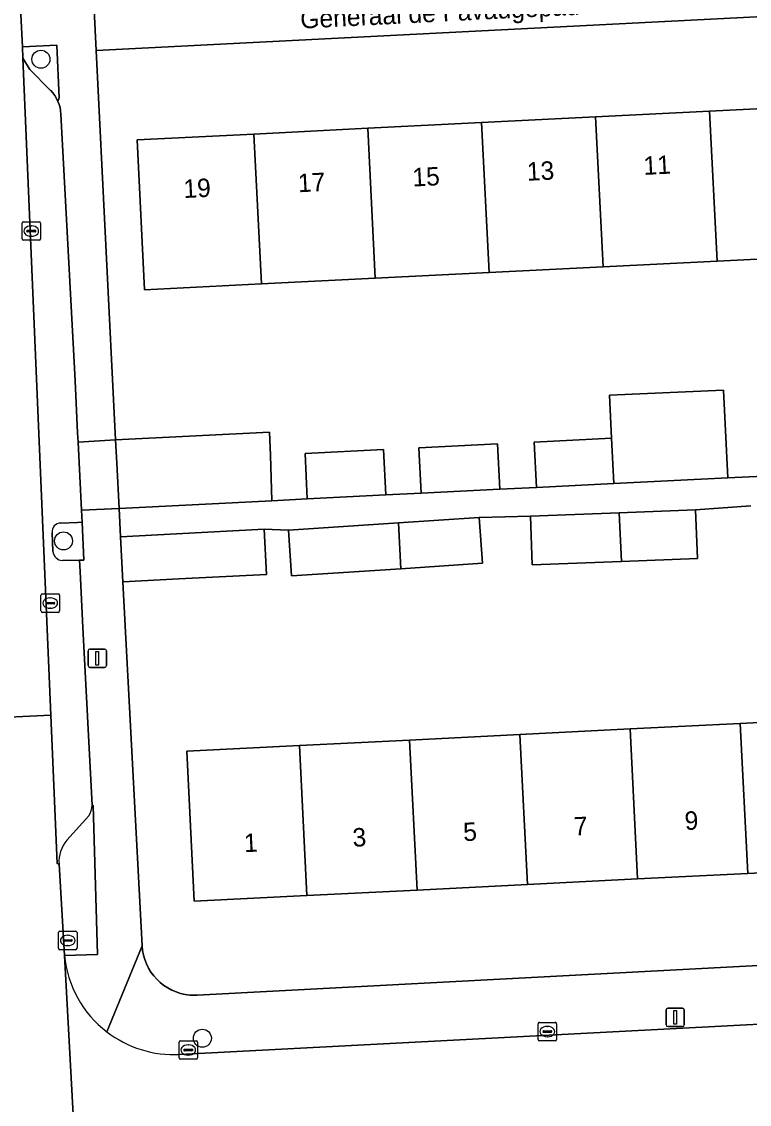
# Model space of a CAD drawing. Extents: x 161084 to 161928, y 385354 to 386522.
# Drawn here: x 161331.4 to 161370.9, y 385913.5 to 385972.3 of the extents above; entities that cross this region are included whole.
import ezdxf

# ---------------------------------------------------------------- set-up
doc = ezdxf.new("R2010")
doc.units = 0
for name, color, linetype in [('IMGEO_Boom', 7, 'Continuous'), ('IMGEO_Erf', 7, 'Continuous'), ('IMGEO_Groenvoorziening', 7, 'Continuous'), ('IMGEO_Kolk', 7, 'Continuous'), ('IMGEO_Lichtmast', 7, 'Continuous'), ('IMGEO_Openbare_ruimte_label', 7, 'Continuous'), ('IMGEO_Pand', 7, 'Continuous'), ('IMGEO_Pand_nummerreeks', 7, 'Continuous'), ('IMGEO_Parkeervlak_open', 7, 'Continuous'), ('IMGEO_Rijbaan_lokaal_open', 7, 'Continuous'), ('IMGEO_Voetpad_open', 7, 'Continuous')]:
    doc.layers.add(name, color=color, linetype=linetype)

msp = doc.modelspace()

# ---------------------------------------------------------------- linework, layer by layer
at = {"layer": 'IMGEO_Boom'}
for centre in [(161332.478, 385970.242), (161333.705, 385944.1), (161341.242, 385917.109)]:
    msp.add_circle(centre, 0.489, dxfattribs=at)
at = {"layer": 'IMGEO_Erf'}
for points in [[(161401.475, 385974.097), (161335.484, 385970.716), (161336.531, 385949.582), (161344.88, 385950.003), (161344.943, 385948.749), (161345.008, 385946.283), (161346.937, 385946.38), (161346.814, 385948.843), (161351.074, 385949.057), (161351.197, 385946.594), (161353.118, 385946.691), (161352.995, 385949.154), (161357.262, 385949.368), (161357.386, 385946.905), (161359.369, 385947.005), (161359.245, 385949.468), (161363.452, 385949.679), (161363.335, 385952.014), (161369.526, 385952.286), (161369.764, 385947.527), (161371.701, 385947.624)], [(161375.356, 385959.598), (161369.174, 385959.288), (161362.991, 385958.977), (161356.809, 385958.667), (161350.627, 385958.357), (161344.445, 385958.046), (161338.11, 385957.728), (161337.701, 385965.867), (161344.036, 385966.185), (161350.218, 385966.496), (161356.4, 385966.806), (161362.582, 385967.116), (161368.765, 385967.427), (161374.947, 385967.737)], [(161371.013, 385946.014), (161368.009, 385945.788), (161368.11, 385943.145), (161363.994, 385942.988), (161359.147, 385942.802), (161359.046, 385945.446), (161356.274, 385945.366), (161356.438, 385942.885), (161352.019, 385942.593), (161346.075, 385942.2), (161345.911, 385944.681), (161344.6, 385944.732), (161344.721, 385942.281), (161339.958, 385942.042), (161336.929, 385941.882), (161337.973, 385922.128), (161337.998, 385921.876), (161338.045, 385921.626), (161338.114, 385921.383), (161338.205, 385921.146), (161338.317, 385920.918), (161338.448, 385920.701), (161338.599, 385920.497), (161338.767, 385920.307), (161338.951, 385920.133), (161339.15, 385919.976), (161339.363, 385919.837), (161339.587, 385919.718), (161339.82, 385919.62), (161340.062, 385919.542), (161340.309, 385919.487), (161340.561, 385919.454), (161340.814, 385919.443), (161340.952, 385919.447), (161401.212, 385922.632)]]:
    msp.add_lwpolyline(points, dxfattribs=at)
msp.add_lwpolyline([(161364.452, 385933.895), (161370.435, 385934.196), (161376.417, 385934.497), (161382.399, 385934.798), (161388.382, 385935.1), (161394.364, 385935.401), (161400.477, 385935.709), (161400.886, 385927.569), (161394.774, 385927.261), (161388.792, 385926.96), (161382.809, 385926.659), (161376.827, 385926.357), (161370.845, 385926.056), (161364.862, 385925.755), (161358.88, 385925.453), (161352.897, 385925.152), (161346.915, 385924.851), (161340.806, 385924.543), (161340.397, 385932.683), (161346.505, 385932.991), (161352.487, 385933.292), (161358.47, 385933.593)], close=True, dxfattribs=at)
at = {"layer": 'IMGEO_Groenvoorziening'}
msp.add_lwpolyline([(161331.473, 385970.92), (161331.504, 385970.309), (161331.875, 385969.691), (161332.988, 385968.573), (161333.013, 385968.548), (161333.131, 385968.414), (161333.236, 385968.27), (161333.328, 385968.118), (161333.406, 385967.957), (161333.477, 385968.154), (161333.342, 385971.017)], close=True, dxfattribs=at)
for points in [[(161334.712, 385945.118), (161334.466, 385945.107), (161333.54, 385945.065)], [(161333.645, 385943.032), (161334.573, 385943.053), (161334.815, 385943.059), (161334.712, 385945.118)], [(161333.092, 385944.554), (161333.131, 385943.524)], [(161333.463, 385926.563), (161333.751, 385921.597), (161335.553, 385921.66), (161335.318, 385929.749)], [(161335.318, 385929.749), (161335.259, 385929.766)], [(161335.083, 385929.174), (161333.892, 385927.851)]]:
    msp.add_lwpolyline(points, dxfattribs=at)
for centre, radius, start, end in [((161333.533, 385944.62), 0.445, 89.03613, 188.48098), ((161333.694, 385943.597), 0.567, 187.42451, 265.08107), ((161334.059, 385929.801), 1.201, 328.53788, 358.34798), ((161335.188, 385926.704), 1.731, 138.48987, 184.66692)]:
    msp.add_arc(centre, radius, start, end, dxfattribs=at)
at = {"layer": 'IMGEO_Kolk'}
for p, q in [((161331.455, 385960.491), (161331.455, 385961.343)), ((161331.53, 385961.417), (161332.382, 385961.417)), ((161331.714, 385960.911), (161331.714, 385960.923)), ((161332.152, 385960.874), (161331.754, 385960.874)), ((161331.757, 385960.96), (161332.155, 385960.96)), ((161331.943, 385961.197), (161331.968, 385961.197)), ((161332.198, 385960.923), (161332.198, 385960.911)), ((161332.456, 385961.343), (161332.456, 385960.491)), ((161332.382, 385960.417), (161331.53, 385960.417)), ((161331.966, 385960.637), (161331.941, 385960.637)), ((161332.484, 385940.299), (161332.484, 385941.151)), ((161332.559, 385941.225), (161333.411, 385941.225)), ((161332.972, 385941.005), (161332.997, 385941.005)), ((161333.485, 385941.151), (161333.485, 385940.299)), ((161332.743, 385940.719), (161332.743, 385940.731)), ((161333.181, 385940.682), (161332.783, 385940.682)), ((161332.786, 385940.768), (161333.184, 385940.768)), ((161332.995, 385940.445), (161332.97, 385940.445)), ((161333.227, 385940.731), (161333.227, 385940.719)), ((161333.411, 385940.225), (161332.559, 385940.225)), ((161333.438, 385921.989), (161333.438, 385922.841)), ((161333.513, 385922.915), (161334.365, 385922.915)), ((161333.926, 385922.695), (161333.951, 385922.695)), ((161334.439, 385922.841), (161334.439, 385921.989)), ((161333.697, 385922.409), (161333.697, 385922.421)), ((161334.135, 385922.372), (161333.737, 385922.372)), ((161333.74, 385922.458), (161334.138, 385922.458)), ((161333.949, 385922.135), (161333.924, 385922.135)), ((161334.181, 385922.421), (161334.181, 385922.409)), ((161334.365, 385921.915), (161333.513, 385921.915)), ((161359.538, 385917.972), (161360.39, 385917.972)), ((161359.463, 385917.046), (161359.463, 385917.898)), ((161359.722, 385917.466), (161359.722, 385917.478)), ((161360.16, 385917.429), (161359.762, 385917.429)), ((161359.765, 385917.515), (161360.163, 385917.515)), ((161359.951, 385917.752), (161359.976, 385917.752)), ((161360.206, 385917.478), (161360.206, 385917.466)), ((161360.464, 385917.898), (161360.464, 385917.046)), ((161339.976, 385916.044), (161339.976, 385916.896)), ((161340.051, 385916.97), (161340.903, 385916.97)), ((161340.977, 385916.896), (161340.977, 385916.044)), ((161360.39, 385916.972), (161359.538, 385916.972)), ((161359.974, 385917.192), (161359.949, 385917.192)), ((161340.235, 385916.464), (161340.235, 385916.476)), ((161340.673, 385916.427), (161340.275, 385916.427)), ((161340.278, 385916.513), (161340.676, 385916.513)), ((161340.464, 385916.75), (161340.489, 385916.75)), ((161340.719, 385916.476), (161340.719, 385916.464)), ((161340.903, 385915.97), (161340.051, 385915.97)), ((161340.487, 385916.19), (161340.462, 385916.19))]:
    msp.add_line(p, q, dxfattribs=at)
for points in [[(161331.455, 385960.491), (161331.455, 385961.343)], [(161331.53, 385961.417), (161332.382, 385961.417)], [(161332.456, 385961.343), (161332.456, 385960.491)], [(161332.382, 385960.417), (161331.53, 385960.417)], [(161332.484, 385940.299), (161332.484, 385941.151)], [(161332.559, 385941.225), (161333.411, 385941.225)], [(161333.485, 385941.151), (161333.485, 385940.299)], [(161333.411, 385940.225), (161332.559, 385940.225)], [(161333.438, 385921.989), (161333.438, 385922.841)], [(161333.513, 385922.915), (161334.365, 385922.915)], [(161334.439, 385922.841), (161334.439, 385921.989)], [(161334.365, 385921.915), (161333.513, 385921.915)], [(161359.538, 385917.972), (161360.39, 385917.972)], [(161359.463, 385917.046), (161359.463, 385917.898)], [(161360.464, 385917.898), (161360.464, 385917.046)], [(161339.976, 385916.044), (161339.976, 385916.896)], [(161340.051, 385916.97), (161340.903, 385916.97)], [(161340.977, 385916.896), (161340.977, 385916.044)], [(161360.39, 385916.972), (161359.538, 385916.972)], [(161340.903, 385915.97), (161340.051, 385915.97)]]:
    msp.add_lwpolyline(points, dxfattribs=at)
for centre, radius, start, end in [((161331.532, 385961.341), 0.0765, 91.55205, 178.44795), ((161331.532, 385961.341), 0.0765, 91.55205, 178.44795), ((161331.754, 385960.92), 0.0403, 85.87752, 175.75265), ((161331.751, 385960.91), 0.0366, 178.93798, 274.71019), ((161332.155, 385960.917), 0.043, 264.86636, 352.45326), ((161332.159, 385960.922), 0.0386, 1.73085, 96.63898), ((161332.38, 385961.341), 0.0765, 1.55205, 88.44795), ((161332.38, 385961.341), 0.0765, 1.55205, 88.44795), ((161331.532, 385960.493), 0.0765, 181.55205, 268.44795), ((161331.532, 385960.493), 0.0765, 181.55205, 268.44795), ((161332.38, 385960.493), 0.0765, 271.55205, 358.44795), ((161332.38, 385960.493), 0.0765, 271.55205, 358.44795), ((161332.561, 385941.149), 0.0765, 91.55205, 178.44795), ((161332.561, 385941.149), 0.0765, 91.55205, 178.44795), ((161333.409, 385941.149), 0.0765, 1.55205, 88.44795), ((161333.409, 385941.149), 0.0765, 1.55205, 88.44795), ((161332.561, 385940.301), 0.0765, 181.55205, 268.44795), ((161332.561, 385940.301), 0.0765, 181.55205, 268.44795), ((161332.783, 385940.728), 0.0403, 85.87752, 175.75265), ((161332.78, 385940.718), 0.0366, 178.93798, 274.71019), ((161333.184, 385940.725), 0.043, 264.86636, 352.45326), ((161333.188, 385940.73), 0.0386, 1.73085, 96.63898), ((161333.409, 385940.301), 0.0765, 271.55205, 358.44795), ((161333.409, 385940.301), 0.0765, 271.55205, 358.44795), ((161333.515, 385922.839), 0.0765, 91.55205, 178.44795), ((161333.515, 385922.839), 0.0765, 91.55205, 178.44795), ((161334.363, 385922.839), 0.0765, 1.55205, 88.44795), ((161334.363, 385922.839), 0.0765, 1.55205, 88.44795), ((161333.737, 385922.418), 0.0403, 85.87752, 175.75265), ((161333.734, 385922.408), 0.0366, 178.93798, 274.71019), ((161334.138, 385922.415), 0.043, 264.86636, 352.45326), ((161334.142, 385922.42), 0.0386, 1.73085, 96.63898), ((161333.515, 385921.991), 0.0765, 181.55205, 268.44795), ((161333.515, 385921.991), 0.0765, 181.55205, 268.44795), ((161334.363, 385921.991), 0.0765, 271.55205, 358.44795), ((161334.363, 385921.991), 0.0765, 271.55205, 358.44795), ((161359.54, 385917.896), 0.0765, 91.55205, 178.44795), ((161359.54, 385917.896), 0.0765, 91.55205, 178.44795), ((161360.388, 385917.896), 0.0765, 1.55205, 88.44795), ((161360.388, 385917.896), 0.0765, 1.55205, 88.44795), ((161359.762, 385917.475), 0.0403, 85.87752, 175.75265), ((161359.759, 385917.465), 0.0366, 178.93798, 274.71019), ((161360.163, 385917.472), 0.043, 264.86636, 352.45326), ((161360.167, 385917.477), 0.0386, 1.73085, 96.63898), ((161340.053, 385916.894), 0.0765, 91.55205, 178.44795), ((161340.053, 385916.894), 0.0765, 91.55205, 178.44795), ((161340.901, 385916.894), 0.0765, 1.55205, 88.44795), ((161340.901, 385916.894), 0.0765, 1.55205, 88.44795), ((161359.54, 385917.048), 0.0765, 181.55205, 268.44795), ((161359.54, 385917.048), 0.0765, 181.55205, 268.44795), ((161360.388, 385917.048), 0.0765, 271.55205, 358.44795), ((161360.388, 385917.048), 0.0765, 271.55205, 358.44795), ((161340.275, 385916.473), 0.0403, 85.87752, 175.75265), ((161340.272, 385916.463), 0.0366, 178.93798, 274.71019), ((161340.676, 385916.47), 0.043, 264.86636, 352.45326), ((161340.68, 385916.475), 0.0386, 1.73085, 96.63898), ((161340.053, 385916.046), 0.0765, 181.55205, 268.44795), ((161340.053, 385916.046), 0.0765, 181.55205, 268.44795), ((161340.901, 385916.046), 0.0765, 271.55205, 358.44795), ((161340.901, 385916.046), 0.0765, 271.55205, 358.44795)]:
    msp.add_arc(centre, radius, start, end, dxfattribs=at)
for centre, major_axis, ratio, start_param, end_param in [((161331.942, 385960.917), (-0.387, 0.002), 0.722429, 4.712389, 7.853982), ((161331.967, 385960.917), (-0.39, 0.002), 0.717154, 1.570796, 4.712389), ((161332.971, 385940.725), (-0.387, 0.002), 0.722429, 4.712389, 7.853982), ((161332.996, 385940.725), (-0.39, 0.002), 0.717154, 1.570796, 4.712389), ((161333.925, 385922.415), (-0.387, 0.002), 0.722429, 4.712389, 7.853982), ((161333.95, 385922.415), (-0.39, 0.002), 0.717154, 1.570796, 4.712389), ((161359.95, 385917.472), (-0.387, 0.002), 0.722429, 4.712389, 7.853982), ((161359.975, 385917.472), (-0.39, 0.002), 0.717154, 1.570796, 4.712389), ((161340.463, 385916.47), (-0.387, 0.002), 0.722429, 4.712389, 7.853982), ((161340.488, 385916.47), (-0.39, 0.002), 0.717154, 1.570796, 4.712389)]:
    msp.add_ellipse(centre, major_axis=major_axis, ratio=ratio, start_param=start_param, end_param=end_param, dxfattribs=at)
at = {"layer": 'IMGEO_Lichtmast'}
for p, q in [((161335.04, 385937.332), (161335.04, 385938.132)), ((161335.04, 385938.132), (161335.04, 385937.332)), ((161335.14, 385938.232), (161335.93, 385938.232)), ((161335.93, 385938.232), (161335.14, 385938.232)), ((161336.03, 385938.132), (161336.03, 385937.332)), ((161336.03, 385937.332), (161336.03, 385938.132)), ((161335.93, 385937.232), (161335.14, 385937.232)), ((161335.14, 385937.232), (161335.93, 385937.232)), ((161366.41, 385917.842), (161366.41, 385918.642)), ((161366.41, 385918.642), (161366.41, 385917.842)), ((161366.51, 385918.742), (161367.3, 385918.742)), ((161367.3, 385918.742), (161366.51, 385918.742)), ((161367.4, 385918.642), (161367.4, 385917.842)), ((161367.4, 385917.842), (161367.4, 385918.642)), ((161367.3, 385917.742), (161366.51, 385917.742)), ((161366.51, 385917.742), (161367.3, 385917.742))]:
    msp.add_line(p, q, dxfattribs=at)
for points in [[(161335.46, 385938.107), (161335.61, 385938.107), (161335.61, 385937.357), (161335.46, 385937.357), (161335.46, 385938.107)], [(161366.83, 385918.617), (161366.98, 385918.617), (161366.98, 385917.867), (161366.83, 385917.867), (161366.83, 385918.617)]]:
    msp.add_lwpolyline(points, dxfattribs=at)
for centre, start, end in [((161335.14, 385938.132), 90, 180), ((161335.14, 385938.132), 90, 180), ((161335.93, 385938.132), 0, 90), ((161335.93, 385938.132), 360, 90), ((161335.14, 385937.332), 180, 270), ((161335.14, 385937.332), 180, 270), ((161335.93, 385937.332), 270, 0), ((161335.93, 385937.332), 270, 0), ((161366.51, 385918.642), 90, 180), ((161366.51, 385918.642), 90, 180), ((161367.3, 385918.642), 0, 90), ((161367.3, 385918.642), 360, 90), ((161366.51, 385917.842), 180, 270), ((161366.51, 385917.842), 180, 270), ((161367.3, 385917.842), 270, 0), ((161367.3, 385917.842), 270, 0)]:
    msp.add_arc(centre, 0.1, start, end, dxfattribs=at)
at = {"layer": 'IMGEO_Pand'}
for points in [[(161362.991, 385958.977), (161369.174, 385959.288), (161368.765, 385967.427), (161362.582, 385967.116)], [(161374.947, 385967.737), (161368.765, 385967.427), (161369.174, 385959.288), (161375.356, 385959.598)], [(161350.627, 385958.357), (161356.809, 385958.667), (161356.4, 385966.806), (161350.218, 385966.496)], [(161362.582, 385967.116), (161356.4, 385966.806), (161356.809, 385958.667), (161362.991, 385958.977)], [(161344.036, 385966.185), (161337.701, 385965.867), (161338.11, 385957.728), (161344.445, 385958.046)], [(161350.218, 385966.496), (161344.036, 385966.185), (161344.445, 385958.046), (161350.627, 385958.357)], [(161369.526, 385952.286), (161363.335, 385952.014), (161363.452, 385949.679), (161363.575, 385947.216), (161369.764, 385947.527)], [(161336.594, 385948.33), (161336.718, 385945.867), (161345.008, 385946.283), (161344.943, 385948.749), (161344.88, 385950.003), (161336.531, 385949.582)], [(161357.262, 385949.368), (161352.995, 385949.154), (161353.118, 385946.691), (161357.386, 385946.905)], [(161363.452, 385949.679), (161359.245, 385949.468), (161359.369, 385947.005), (161363.575, 385947.216)], [(161351.074, 385949.057), (161346.814, 385948.843), (161346.937, 385946.38), (161351.197, 385946.594)], [(161363.994, 385942.988), (161363.861, 385945.63), (161359.046, 385945.446), (161359.147, 385942.802)], [(161363.861, 385945.63), (161363.994, 385942.988), (161368.11, 385943.145), (161368.009, 385945.788)], [(161352.019, 385942.593), (161351.893, 385945.076), (161345.911, 385944.681), (161346.075, 385942.2)], [(161351.893, 385945.076), (161352.019, 385942.593), (161356.438, 385942.885), (161356.274, 385945.366)], [(161336.929, 385941.882), (161339.958, 385942.042), (161344.721, 385942.281), (161344.6, 385944.732), (161339.835, 385944.492), (161336.799, 385944.332)], [(161370.845, 385926.056), (161376.827, 385926.357), (161376.417, 385934.497), (161370.435, 385934.196)], [(161358.88, 385925.453), (161364.862, 385925.755), (161364.452, 385933.895), (161358.47, 385933.593)], [(161370.435, 385934.196), (161364.452, 385933.895), (161364.862, 385925.755), (161370.845, 385926.056)], [(161346.915, 385924.851), (161352.897, 385925.152), (161352.487, 385933.292), (161346.505, 385932.991)], [(161358.47, 385933.593), (161352.487, 385933.292), (161352.897, 385925.152), (161358.88, 385925.453)], [(161346.505, 385932.991), (161340.397, 385932.683), (161340.806, 385924.543), (161346.915, 385924.851)]]:
    msp.add_lwpolyline(points, close=True, dxfattribs=at)
at = {"layer": 'IMGEO_Parkeervlak_open'}
for points in [[(161334.496, 385949.462), (161334.471, 385949.961), (161334.331, 385952.782), (161334.294, 385953.481), (161333.568, 385967.267), (161333.551, 385967.444), (161333.518, 385967.619), (161333.47, 385967.791), (161333.406, 385967.957), (161333.328, 385968.118), (161333.236, 385968.27), (161333.131, 385968.414), (161333.013, 385968.548), (161332.988, 385968.573), (161331.875, 385969.691), (161331.504, 385970.309), (161333.016, 385934.637), (161333.357, 385926.589), (161333.463, 385926.563)], [(161333.54, 385945.065), (161334.466, 385945.107), (161334.712, 385945.118), (161334.68, 385945.766), (161334.496, 385949.462)], [(161333.131, 385943.524), (161333.092, 385944.554)], [(161335.259, 385929.766), (161334.763, 385939.397), (161334.605, 385942.434), (161334.573, 385943.053), (161333.645, 385943.032)], [(161333.892, 385927.851), (161335.083, 385929.174)]]:
    msp.add_lwpolyline(points, dxfattribs=at)
for centre, radius, start, end in [((161333.533, 385944.62), 0.445, 89.03613, 188.48098), ((161333.694, 385943.597), 0.567, 187.42451, 265.08107), ((161334.059, 385929.801), 1.201, 328.53788, 358.34798), ((161335.188, 385926.704), 1.731, 138.48987, 184.66692)]:
    msp.add_arc(centre, radius, start, end, dxfattribs=at)
at = {"layer": 'IMGEO_Rijbaan_lokaal_open'}
for points in [[(161326.147, 385934.319), (161333.016, 385934.637), (161331.504, 385970.309), (161331.473, 385970.92), (161331.366, 385973.031)], [(161333.751, 385921.597), (161334.753, 385903.342)], [(161402.248, 385919.484), (161339.999, 385916.229)]]:
    msp.add_lwpolyline(points, dxfattribs=at)
msp.add_lwpolyline([(161333.751, 385921.597), (161333.463, 385926.563), (161333.357, 385926.589), (161333.016, 385934.637), (161326.147, 385934.319), (161326.504, 385927.19), (161326.775, 385921.826), (161326.911, 385917.871), (161327.272, 385911.086), (161327.453, 385906.058), (161327.894, 385899.154), (161328.221, 385893.233), (161328.611, 385886.679), (161328.848, 385880.052), (161335.848, 385880.425), (161334.76, 385903.056), (161334.753, 385903.342)], close=True, dxfattribs=at)
for centre, radius, start, end in [((161339.701, 385922.2), 5.98, 185.7885, 232.50846), ((161339.7, 385922.205), 5.984, 232.54803, 272.86657)]:
    msp.add_arc(centre, radius, start, end, dxfattribs=at)
at = {"layer": 'IMGEO_Voetpad_open'}
for points in [[(161335.335, 385973.695), (161335.484, 385970.716), (161401.475, 385974.097)], [(161331.366, 385973.031), (161331.473, 385970.92), (161333.342, 385971.017), (161333.477, 385968.154), (161333.406, 385967.957), (161333.47, 385967.791), (161333.518, 385967.619), (161333.551, 385967.444), (161333.568, 385967.267), (161334.294, 385953.481), (161334.331, 385952.782), (161334.471, 385949.961), (161334.496, 385949.462), (161336.531, 385949.582), (161335.484, 385970.716), (161335.335, 385973.695)], [(161371.701, 385947.624), (161369.764, 385947.527), (161363.575, 385947.216), (161359.369, 385947.005), (161357.386, 385946.905), (161353.118, 385946.691), (161351.197, 385946.594), (161346.937, 385946.38), (161345.008, 385946.283), (161336.718, 385945.867), (161336.799, 385944.332), (161339.835, 385944.492), (161344.6, 385944.732), (161345.911, 385944.681), (161351.893, 385945.076), (161356.274, 385945.366), (161359.046, 385945.446), (161363.861, 385945.63), (161368.009, 385945.788), (161371.013, 385946.014)], [(161336.929, 385941.882), (161336.799, 385944.332), (161336.718, 385945.867), (161334.68, 385945.766), (161334.712, 385945.118), (161334.815, 385943.059), (161334.573, 385943.053), (161334.605, 385942.434), (161334.763, 385939.397), (161335.259, 385929.766), (161335.318, 385929.749), (161335.553, 385921.66), (161333.751, 385921.597)], [(161336.061, 385917.455), (161337.973, 385922.128), (161336.929, 385941.882)], [(161401.212, 385922.632), (161340.952, 385919.447), (161340.814, 385919.443), (161340.561, 385919.454), (161340.309, 385919.487), (161340.062, 385919.542), (161339.82, 385919.62), (161339.587, 385919.718), (161339.363, 385919.837), (161339.15, 385919.976), (161338.951, 385920.133), (161338.767, 385920.307), (161338.599, 385920.497), (161338.448, 385920.701), (161338.317, 385920.918), (161338.205, 385921.146), (161338.114, 385921.383), (161338.045, 385921.626), (161337.998, 385921.876), (161337.973, 385922.128), (161336.061, 385917.455)], [(161339.999, 385916.229), (161402.248, 385919.484)]]:
    msp.add_lwpolyline(points, dxfattribs=at)
msp.add_lwpolyline([(161334.68, 385945.766), (161336.718, 385945.867), (161336.594, 385948.33), (161336.531, 385949.582), (161334.496, 385949.462)], close=True, dxfattribs=at)
for centre, radius, start, end in [((161339.701, 385922.2), 5.98, 185.7885, 232.50846), ((161339.7, 385922.205), 5.984, 232.54803, 272.86657)]:
    msp.add_arc(centre, radius, start, end, dxfattribs=at)

# ---------------------------------------------------------------- texts
at = {"layer": 'IMGEO_Openbare_ruimte_label'}
msp.add_text('Generaal de Favaugepad', height=1, rotation=2.86527, dxfattribs=at).set_placement((161346.58, 385971.906))
at = {"layer": 'IMGEO_Pand_nummerreeks'}
for s, rotation, p in [('11', 2.87478, (161365.203, 385963.964)), ('15', 2.87478, (161352.664, 385963.334)), ('13', 2.87478, (161358.877, 385963.646)), ('17', 2.87478, (161346.451, 385963.022)), ('19', 2.87478, (161340.238, 385962.71)), ('7', 2.88333, (161361.432, 385928.104)), ('9', 2.88333, (161367.44, 385928.407)), ('3', 2.88333, (161349.416, 385927.499)), ('5', 2.88333, (161355.424, 385927.802)), ('1', 2.88333, (161343.522, 385927.203))]:
    msp.add_text(s, height=1, rotation=rotation, dxfattribs=at).set_placement(p)

doc.saveas('drawing.dxf')
